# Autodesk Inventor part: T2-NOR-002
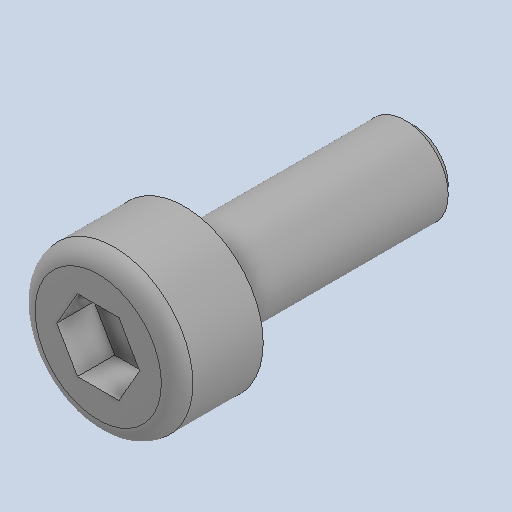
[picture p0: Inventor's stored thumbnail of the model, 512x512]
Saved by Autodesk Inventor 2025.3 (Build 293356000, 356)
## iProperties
Created: 2020-02
Part Number: T2-NOR-002
Material: Genérico
Description: Tornillo de cabeza cilíndrica con hexágono interior M3 × 8 mm
Document SubType Name: Modeling
Designer: Luis MuÃ±oz
Authority: Unknown
Density: 1 g/cm^3
Appearance: Valor por defecto
Project: TESIS 2 - Plataforma mecatrÃ³nica preventiva desacoplada
Sending System: FreeCAD
Preprocessor: Open CASCADE STEP processor 7.3
Title: Tornillo de cabeza cilÃ­ndrica con hexÃ¡gono interior M3 Ã— 8 mm
Author: Author
Revision Number: 00
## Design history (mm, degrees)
feature "Base1"
node "Sólido1"
